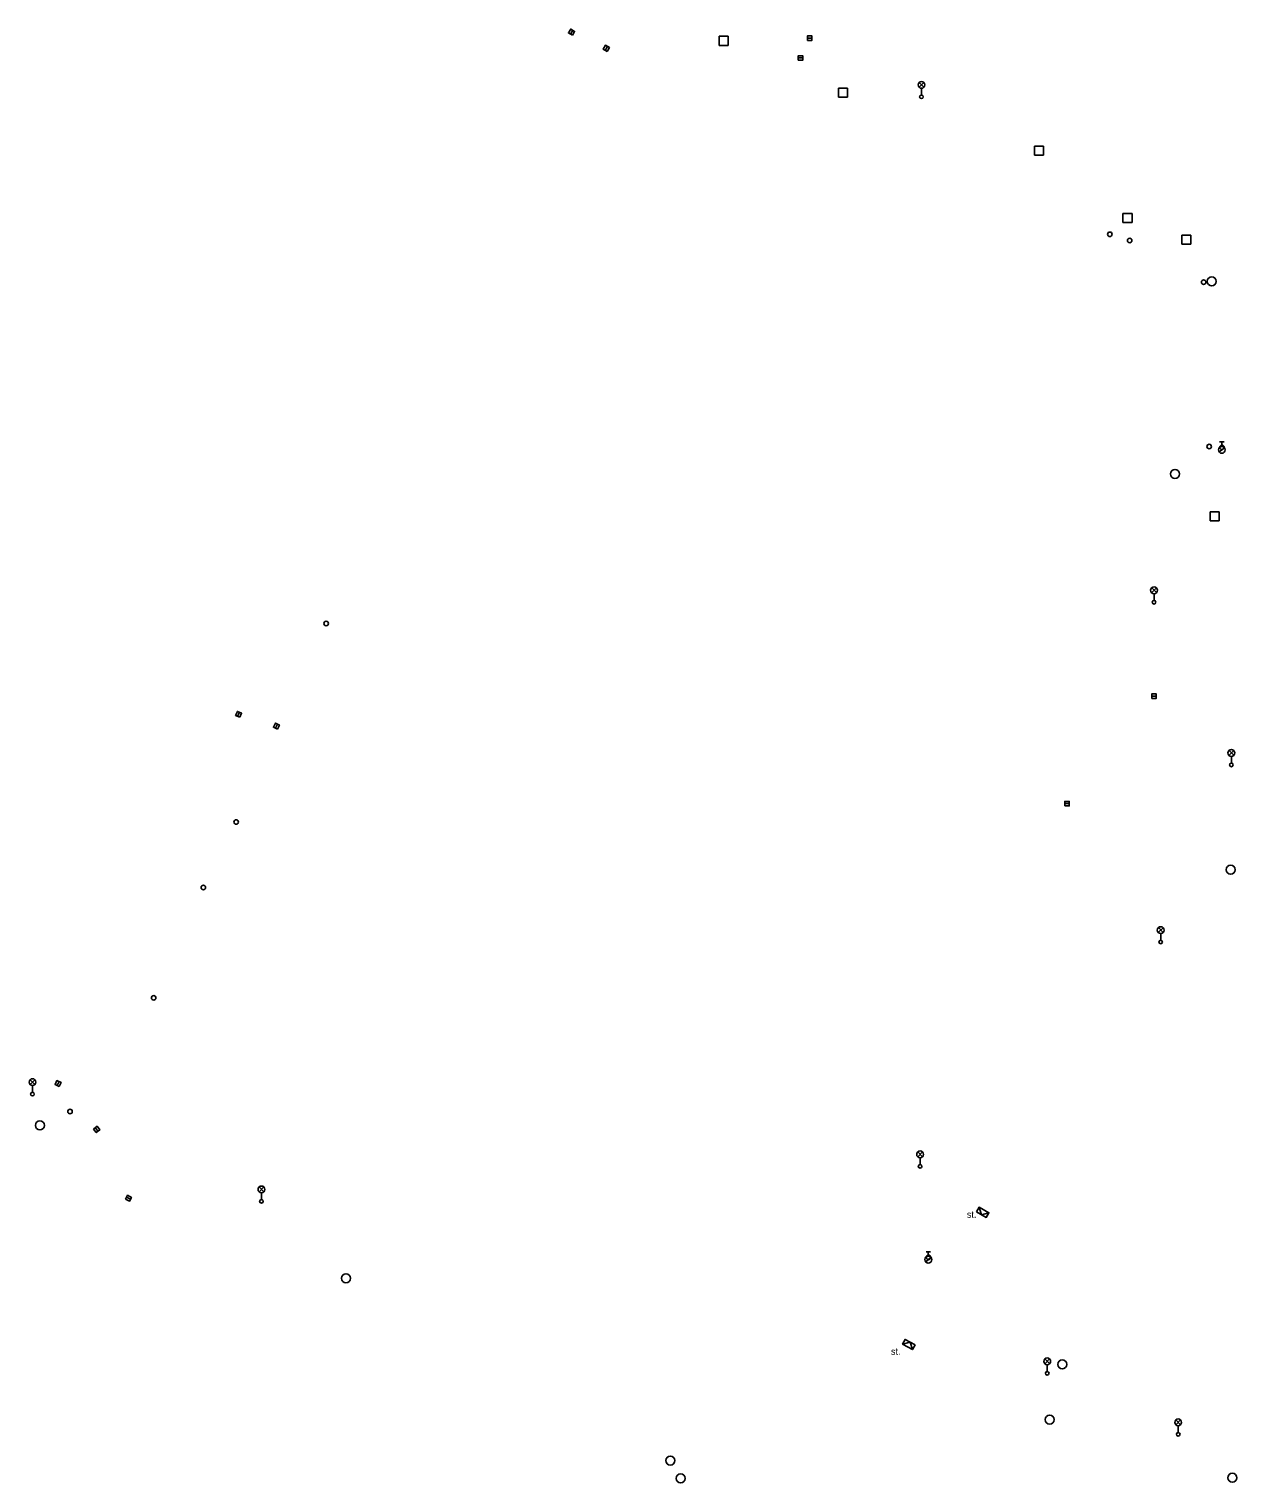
# Model space of a CAD drawing. Extents: x -762383 to -761269, y -1154974 to -1154183.
# Drawn here: x -762113.1 to -761979.2, y -1154971.2 to -1154810 of the extents above; entities that cross this region are included whole.
import ezdxf

# ---------------------------------------------------------------- set-up
doc = ezdxf.new("R2010")
doc.units = 0
for name, color, linetype in [('Vrstva 1', 7, 'Continuous'), ('Vrstva 2', 7, 'Continuous'), ('Vrstva 9', 7, 'Continuous')]:
    doc.layers.add(name, color=color, linetype=linetype)

msp = doc.modelspace()

# ---------------------------------------------------------------- linework, layer by layer
at = {"layer": 'Vrstva 1'}
for points in [[(-762008.067, -1154941.148), (-762006.973, -1154941.752), (-762006.683, -1154941.226), (-762007.778, -1154940.623)], [(-762014.873, -1154955.873), (-762015.967, -1154955.267), (-762016.258, -1154955.792), (-762015.164, -1154956.398)]]:
    msp.add_lwpolyline(points, close=True, dxfattribs=at)
for points in [[(-762007.778, -1154940.623), (-762007.52, -1154941.45), (-762006.683, -1154941.226)], [(-762015.164, -1154956.398), (-762015.42, -1154955.57), (-762016.258, -1154955.792)]]:
    msp.add_lwpolyline(points, dxfattribs=at)
at = {"layer": 'Vrstva 9'}
for p, q in [((-762053.075, -1154810.597), (-762052.825, -1154810.163)), ((-762035.57, -1154810.84), (-762036.57, -1154810.84)), ((-762036.57, -1154810.84), (-762036.57, -1154811.84)), ((-762035.57, -1154811.84), (-762035.57, -1154810.84)), ((-762026.81, -1154811.04), (-762026.31, -1154811.04)), ((-762049.225, -1154812.397), (-762048.975, -1154811.963)), ((-762036.57, -1154811.84), (-762035.57, -1154811.84)), ((-762027.82, -1154813.24), (-762027.32, -1154813.24)), ((-762014.424, -1154816.488), (-762013.896, -1154815.96)), ((-762013.888, -1154816.485), (-762014.416, -1154815.956)), ((-762022.36, -1154816.6), (-762023.36, -1154816.6)), ((-762023.36, -1154816.6), (-762023.36, -1154817.6)), ((-762023.36, -1154817.6), (-762022.36, -1154817.6)), ((-762022.36, -1154817.6), (-762022.36, -1154816.6)), ((-762014.16, -1154816.6), (-762014.16, -1154817.35)), ((-762000.64, -1154823.01), (-762001.64, -1154823.01)), ((-762001.64, -1154823.01), (-762001.64, -1154824.01)), ((-762001.64, -1154824.01), (-762000.64, -1154824.01)), ((-762000.64, -1154824.01), (-762000.64, -1154823.01)), ((-761990.82, -1154830.47), (-761991.82, -1154830.47)), ((-761991.82, -1154830.47), (-761991.82, -1154831.47)), ((-761990.82, -1154831.47), (-761990.82, -1154830.47)), ((-761991.82, -1154831.47), (-761990.82, -1154831.47)), ((-761984.29, -1154832.87), (-761985.29, -1154832.87)), ((-761985.29, -1154832.87), (-761985.29, -1154833.87)), ((-761984.29, -1154833.87), (-761984.29, -1154832.87)), ((-761985.29, -1154833.87), (-761984.29, -1154833.87)), ((-761981.11, -1154855.805), (-761980.61, -1154855.805)), ((-761980.86, -1154856.305), (-761980.86, -1154855.805)), ((-761981.154, -1154856.911), (-761980.564, -1154856.448)), ((-761981.16, -1154863.55), (-761982.16, -1154863.55)), ((-761982.16, -1154863.55), (-761982.16, -1154864.55)), ((-761981.16, -1154864.55), (-761981.16, -1154863.55)), ((-761982.16, -1154864.55), (-761981.16, -1154864.55)), ((-761988.644, -1154872.508), (-761988.116, -1154871.98)), ((-761988.108, -1154872.505), (-761988.636, -1154871.976)), ((-761988.38, -1154872.62), (-761988.38, -1154873.37)), ((-761988.63, -1154883.98), (-761988.13, -1154883.98)), ((-762089.962, -1154886.218), (-762089.758, -1154885.762)), ((-762085.767, -1154887.526), (-762085.553, -1154887.074)), ((-761980.074, -1154890.538), (-761979.546, -1154890.01)), ((-761979.538, -1154890.535), (-761980.066, -1154890.006)), ((-761979.81, -1154890.65), (-761979.81, -1154891.4)), ((-761998.28, -1154895.89), (-761997.78, -1154895.89)), ((-761987.904, -1154910.168), (-761987.376, -1154909.64)), ((-761987.368, -1154910.165), (-761987.896, -1154909.636)), ((-761987.64, -1154910.28), (-761987.64, -1154911.03)), ((-762112.974, -1154927.018), (-762112.446, -1154926.49)), ((-762112.438, -1154927.015), (-762112.966, -1154926.486)), ((-762112.71, -1154927.13), (-762112.71, -1154927.88)), ((-762109.974, -1154927.137), (-762109.766, -1154926.683)), ((-762105.752, -1154931.802), (-762105.448, -1154932.198)), ((-762014.574, -1154935.028), (-762014.046, -1154934.5)), ((-762014.038, -1154935.025), (-762014.566, -1154934.496)), ((-762014.31, -1154935.14), (-762014.31, -1154935.89)), ((-762087.594, -1154938.908), (-762087.066, -1154938.38)), ((-762087.058, -1154938.905), (-762087.586, -1154938.376)), ((-762102.291, -1154939.513), (-762101.849, -1154939.747)), ((-762087.33, -1154939.02), (-762087.33, -1154939.77)), ((-762013.694, -1154946.661), (-762013.104, -1154946.198)), ((-762013.65, -1154945.555), (-762013.15, -1154945.555)), ((-762013.4, -1154946.055), (-762013.4, -1154945.555)), ((-762000.484, -1154957.968), (-761999.956, -1154957.44)), ((-761999.948, -1154957.965), (-762000.476, -1154957.436)), ((-762000.22, -1154958.08), (-762000.22, -1154958.83)), ((-761985.964, -1154964.728), (-761985.436, -1154964.2)), ((-761985.428, -1154964.725), (-761985.956, -1154964.196)), ((-761985.7, -1154964.84), (-761985.7, -1154965.59))]:
    msp.add_line(p, q, dxfattribs=at)
for points in [[(-762052.858, -1154810.722), (-762052.607, -1154810.289), (-762053.042, -1154810.038), (-762053.292, -1154810.471)], [(-762026.81, -1154811.291), (-762026.31, -1154811.291), (-762026.31, -1154810.79), (-762026.81, -1154810.79)], [(-762049.008, -1154812.522), (-762048.757, -1154812.089), (-762049.192, -1154811.838), (-762049.442, -1154812.271)], [(-762027.82, -1154813.491), (-762027.32, -1154813.491), (-762027.32, -1154812.99), (-762027.82, -1154812.99)], [(-761988.63, -1154884.231), (-761988.13, -1154884.231), (-761988.13, -1154883.73), (-761988.63, -1154883.73)], [(-762089.732, -1154886.32), (-762089.529, -1154885.863), (-762089.987, -1154885.659), (-762090.19, -1154886.117)], [(-762085.54, -1154887.633), (-762085.326, -1154887.181), (-762085.779, -1154886.966), (-762085.993, -1154887.418)], [(-761998.28, -1154896.141), (-761997.78, -1154896.141), (-761997.78, -1154895.64), (-761998.28, -1154895.64)], [(-762109.746, -1154927.242), (-762109.538, -1154926.786), (-762109.994, -1154926.578), (-762110.202, -1154927.033)], [(-762105.951, -1154931.954), (-762105.647, -1154932.352), (-762105.249, -1154932.046), (-762105.553, -1154931.649)], [(-762102.409, -1154939.734), (-762101.967, -1154939.969), (-762101.731, -1154939.527), (-762102.173, -1154939.291)]]:
    msp.add_lwpolyline(points, close=True, dxfattribs=at)
for centre, radius in [((-762014.16, -1154816.225), 0.375), ((-762014.16, -1154817.55), 0.2), ((-761993.27, -1154832.78), 0.25), ((-761991.08, -1154833.47), 0.25), ((-761982.88, -1154838.09), 0.25), ((-761981.98, -1154838), 0.5), ((-761982.26, -1154856.31), 0.25), ((-761980.86, -1154856.68), 0.375), ((-761980.84, -1154856.39), 0.25), ((-761986.06, -1154859.35), 0.5), ((-761988.38, -1154872.245), 0.375), ((-761988.38, -1154873.57), 0.2), ((-762080.15, -1154875.92), 0.25), ((-761979.81, -1154890.275), 0.375), ((-761979.81, -1154891.6), 0.2), ((-762090.13, -1154897.93), 0.25), ((-761979.88, -1154903.21), 0.5), ((-762093.76, -1154905.18), 0.25), ((-761987.64, -1154909.905), 0.375), ((-761987.64, -1154911.23), 0.2), ((-762099.27, -1154917.42), 0.25), ((-762112.71, -1154926.755), 0.375), ((-762112.71, -1154928.08), 0.2), ((-762108.54, -1154930.02), 0.25), ((-762111.89, -1154931.55), 0.5), ((-762014.31, -1154934.765), 0.375), ((-762014.31, -1154936.09), 0.2), ((-762087.33, -1154938.645), 0.375), ((-762087.33, -1154939.97), 0.2), ((-762013.4, -1154946.43), 0.375), ((-762013.39, -1154946.18), 0.25), ((-762077.96, -1154948.5), 0.5), ((-762000.22, -1154957.705), 0.375), ((-761998.56, -1154958.04), 0.5), ((-762000.22, -1154959.03), 0.2), ((-761999.94, -1154964.16), 0.5), ((-761985.7, -1154964.465), 0.375), ((-761985.7, -1154965.79), 0.2), ((-762042, -1154968.7), 0.5), ((-762040.86, -1154970.68), 0.5), ((-761979.69, -1154970.61), 0.5)]:
    msp.add_circle(centre, radius, dxfattribs=at)

# ---------------------------------------------------------------- texts
at = {"layer": 'Vrstva 2'}
for p in [(-762009.13, -1154941.8), (-762017.54, -1154956.98)]:
    msp.add_text('st.', height=0.75, dxfattribs=at).set_placement(p)

doc.saveas('drawing.dxf')
